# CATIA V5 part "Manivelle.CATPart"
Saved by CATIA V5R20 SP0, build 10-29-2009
Part number: Manivelle
Bounding box of the stored display mesh (mm): x -16 to 15, y -6 to 33.953, z 4 to 26.891
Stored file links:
  D:\Dropbox\IAO_2011\MMS_GR2\IAO_2011_1495_fpittorino\fpittorino_IAO\IAO_2011_1495_fpittorino\Manivelle.CATPart
  D:\Dropbox\IAO_2011\MMS_GR2\IAO_2011_1495_fpittorino\fpittorino_IAO\IAO_2011_1495_fpittorino\Product3.CATProduct
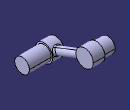
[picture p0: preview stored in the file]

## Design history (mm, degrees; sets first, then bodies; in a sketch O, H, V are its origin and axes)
Set1
  Plane1: linked copy from another document
  Point1: linked copy from another document
  Line1: linked copy from another document
  Point2: linked copy from another document
Body1 (main body)
  Sketch1 on Plane1, origin (0, 0, 0), H (0, 1, 0), V (0, 0, 1)
    circle A1 centre (0, 10) radius 5
    point P1 (0, 10)
    reference projected point E1 (0, 10) from Point1
    radius A1 = 5
    coincidence: P1 E1
  Pad1: profile Sketch1, direction (1, 0, 0), length 15
  Sketch2 on Plane1, origin (0, 0, 0), H (0, 1, 0), V (0, 0, 1)
    circle A1 centre (0, 10) radius 6
    point P1 (0, 10)
    reference projected point E1 (0, 10) from Point1
    circle A2 centre (27.9533, 20.8909) radius 6
    point P2 (27.9533, 20.8909)
    reference projected point E2 (27.9533, 20.8909) from Point2
    radius A1 = 6
    radius A2 = 6
    coincidence: P1 E1, P2 E2
  Pad2: profile Sketch2, direction (-1, 0, 0), length 8
  Plane2: type Offset, RefPlane end face of Pad2, Offset 4
  Sketch3 on Plane2, origin (-4, 27.9533, 20.8909), H (0, 0.9318, 0.363), V (0, -0.363, 0.9318)
    line L1 (0, 0) -> (-30, 0)
    line L2 (-30, 0) -> (-30, 2.5)
    line L3 (-30, 2.5) -> (0, 2.5)
    line L4 (0, 2.5) -> (0, 0)
    point P1 (-30, 0)
    reference projected point E1 (-30, 0) from Point1
    length L4 = 2.5
    horizontal: L1 H, L3 H
    vertical: L2 V, L4 V
    coincidence: P1 E1
  Shaft1: profile Sketch3, axis Sketch3.L1, angle 360
  Sketch4 on end face of Pad2, origin (-8, 27.9533, 20.8909), H (0, -1, 0), V (0, 0, 1)
    circle A1 centre (0, 0) radius 5
    radius A1 = 5
  Pad3: profile Sketch4, direction (-1, 0, 0), length 8
  Fillet1: radius 1, on edge [face of Shaft1 from Sketch3.L3 | face of Pad2 from Sketch2.A1]; edge [face of Pad2 from Sketch2.A2 | face of Shaft1 from Sketch3.L3]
